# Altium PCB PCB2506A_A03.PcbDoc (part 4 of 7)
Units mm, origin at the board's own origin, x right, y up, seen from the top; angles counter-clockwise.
Board outline 115 x 60 mm, 6 copper layers (Top Layer, Signal Layer 2, Signal Layer 3, Signal Layer 4, Signal Layer 5, Bottom Layer), stack 1.555 mm thick; 376 components, 290 nets, 1297 pads, 901 vias.
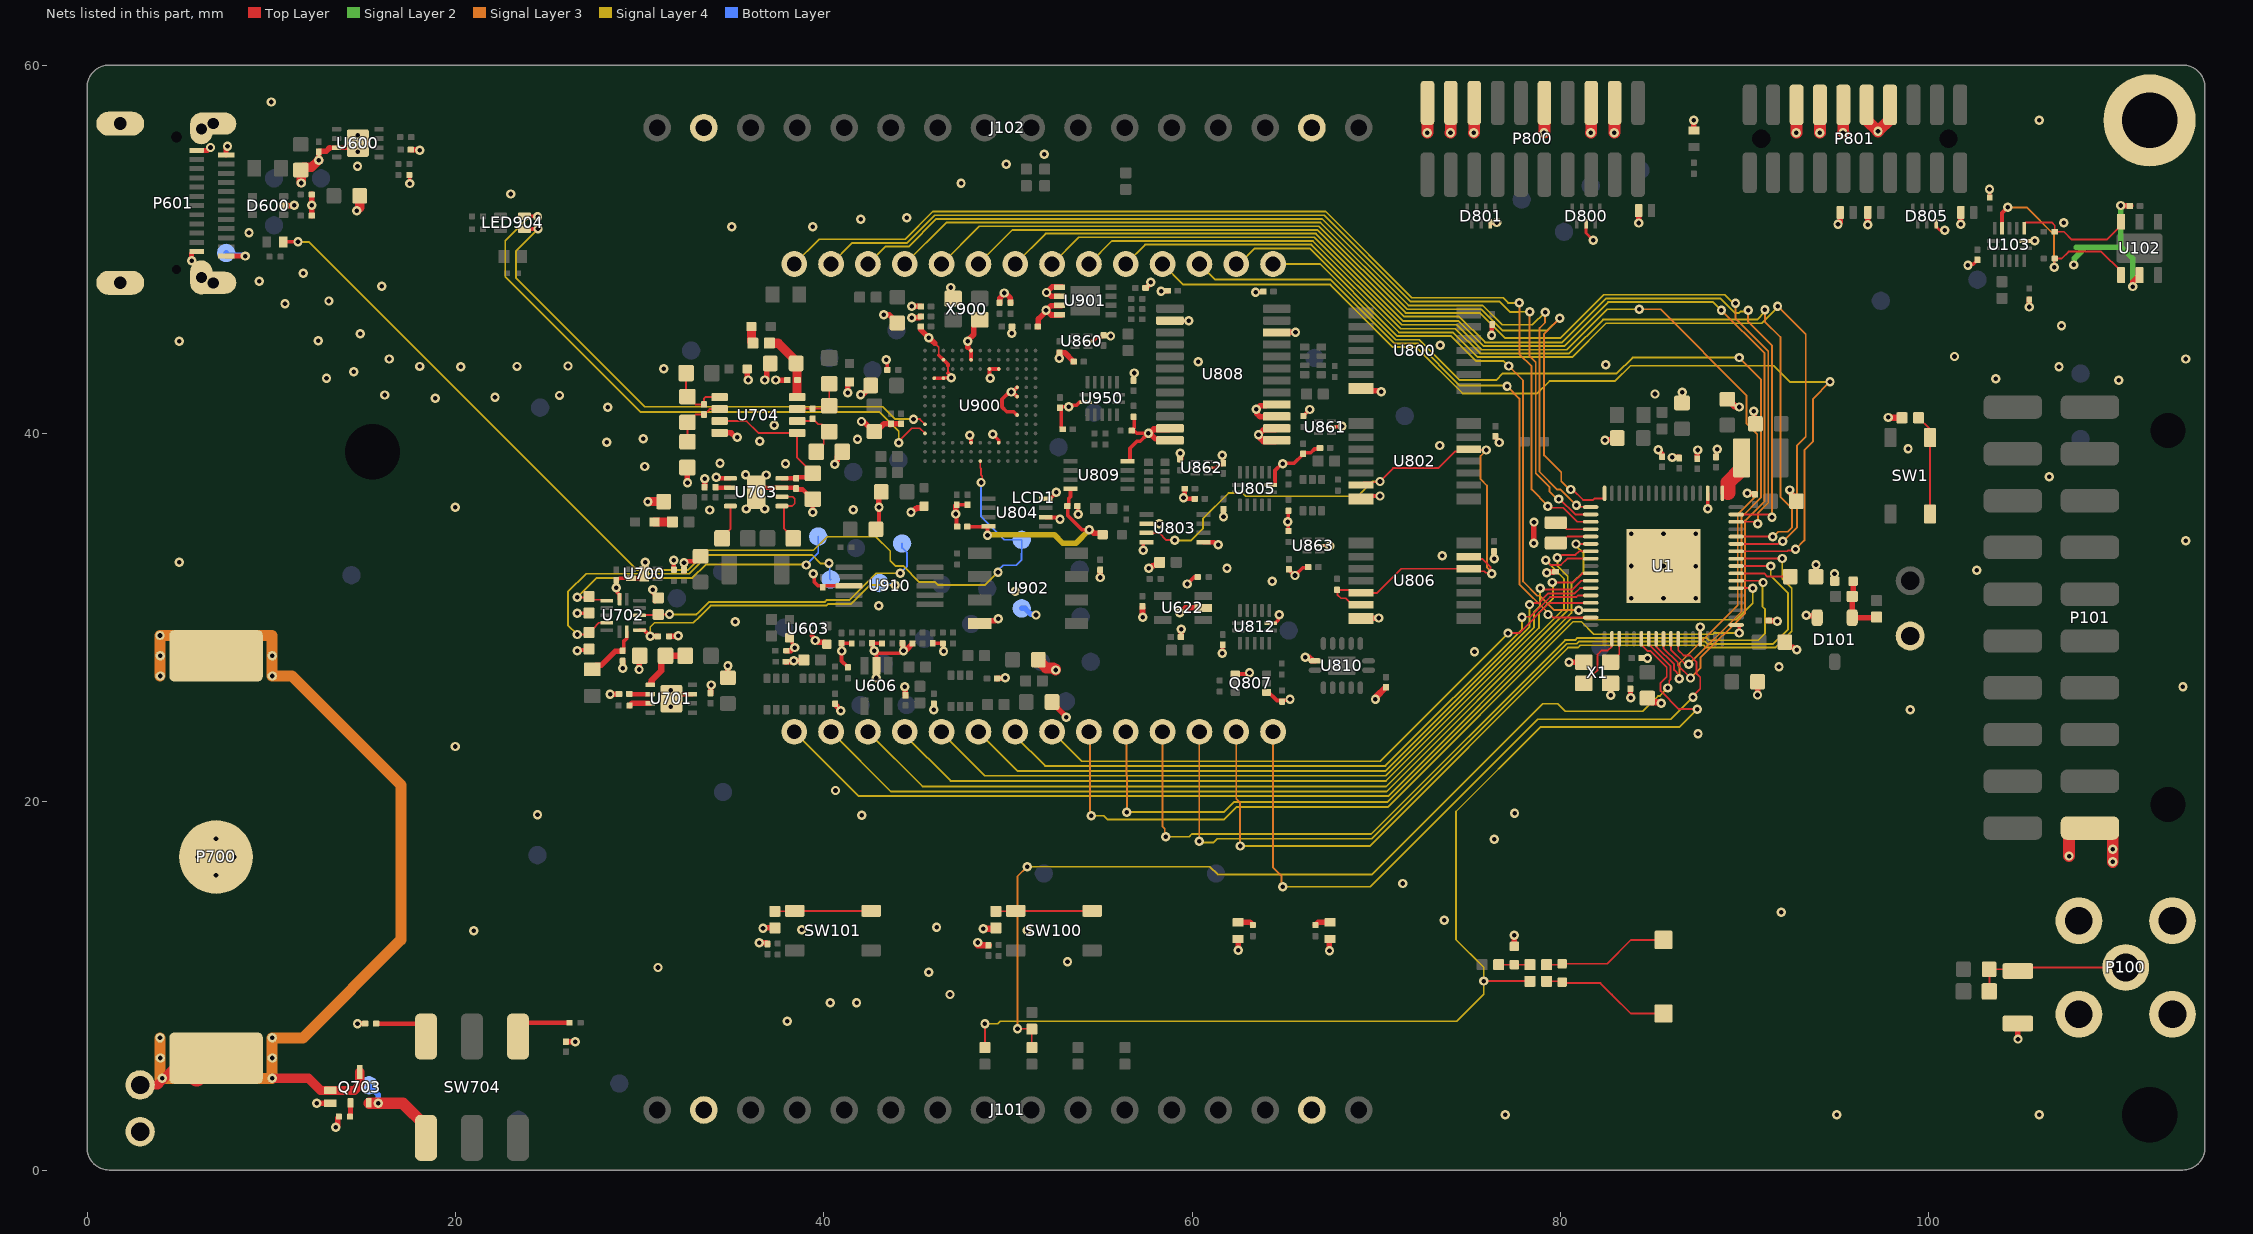
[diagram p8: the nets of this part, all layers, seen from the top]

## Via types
v1: diameter 0.508, hole 0.25, Top Layer to Bottom Layer, tented both sides, 901 vias

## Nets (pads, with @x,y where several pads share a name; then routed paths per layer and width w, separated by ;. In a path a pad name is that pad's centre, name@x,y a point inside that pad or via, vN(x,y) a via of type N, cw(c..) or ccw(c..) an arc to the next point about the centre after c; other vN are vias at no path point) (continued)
GND: C1.2 C2.2 C3.2 C4.2 C5.2 C6.2 C8.2 C9.2 C10.2 C12.2 C13.2 C15.2 C16.2 C17.2 C18.2 C102.2 C103.2 C110.2 C115.2 C117.2 C123.2 C130.2 C501.1 C600.2 C602.2 C607.2 C608.2 C609.2 C610.2 C611.2 C621.2 C625.2 C632.2 C635.2 C638.2 C641.2 C652.2 C653.2 C655.2 C660.2 C673.2 C674.2 C700.2 C701.2 C702.2 C703.2 C705.2 C706.2 C707.2 C708.2 C714.2 C720.2 C724.2 C728.2 C729.2 C730.2 C731.2 C800.2 C803.2 C804.2 C805.2 C806.2 C807.2 C808.2 C809.2 C810.2 C827.2 C828.2 C860.2 C861.2 C862.2 C863.2 C864.2 C865.2 C866.2 C867.2 C900.2 C901.2 C902.2 C903.2 C904.2 C905.2 C906.2 C907.2 C908.2 C909.2 C910.2 C911.2 C914.2 C921.2 C922.2 C924.2 C925.2 C926.2 C927.2 C950.2 C951.2 C952.2 D101.2 D600.2 D703.2 D800.6 D801.7 D805.7 D806.2 D807.2 D808.2 D809.2 J101.2 J101.15 J102.2 J102.15 LED100.2 LED101.2 LED900.2 M1.1 P100.2 P100.3 P100.4 P100.5 P101.1 P601.25@1.8,56.82 P601.26@1.8,48.18 P601.27@6.2,56.525 P601.27@6.85,56.82 P601.28@6.2,48.475 P601.28@6.85,48.18 P601.A1 P601.A12 P601.B1 P601.B12 P700.2 P800.3 P800.5 P800.9 P800.15 P800.17 P800.19 P801.7 P801.9 P801.11 P801.13 P801.15 Q807.1 Q807.4 R7.1 R104.2 R105.2 R112.2 R120.1 R602.1 R620.1 R621.1 R623.1 R628.2 R631.1 R634.1 R637.1 R640.1 R674.2 R688.2 R691.2 R703.1 R705.1 R706.1 R707.1 R708.1 R718.1 R760.1 R763.1 R767.1 R771.1 R792.1 R794.2 R814.1 R839.1 R850.1 R851.1 R852.1 R853.1 R930.2 R931.2 R950.2 R981.2 R985.2 ST701.1 TPH100.1 TPJ614.1 TPJ913.1 U1.31 U1.54 U1.69 U102.2 U103.7 U600.3 U600.9 U603.A1 U606.2 U622.2 U700.2 U700.5 U701.3 U701.9 U702.7 U703.3 U703.5 U703.9 U704.4 U800.7 U802.7 U803.2 U803.4 U803.5 U804.2 U804.4 U805.7 U806.7 U808.2 U808.11 U808.12 U808.13 U808.14 U808.15 U808.16 U808.22 U809.4 U810.7 U812.7 U860.2 U861.2 U862.2 U863.2 U900.C5 U900.C8 U900.F3 U900.H3 U900.J3 U900.K11 U900.K12 U900.L5 U900.L6 U900.M8 U900.M11 U900.N8 U901.1 U901.2 U901.3 U901.4 U902.4 U910.3 U950.7 X1.2 X1.4 X900.2 X900.4 | length 201.6
  Top Layer w0.1: 46.025,44.9 46.25,44.675 46.25,44.25 ; 46.75,43.275 46.75,43.674
  Top Layer w0.15: U862.2@60.873,38.135 61.325,38.135 61.405,38.215 ; v1@65.209,35.211 v1@65.284,35.136 ; U863.2@66.936,33.913 67.448,33.913 v1(67.475,33.885) ; D800.6@81.4,51.385 81.4,50.879 v1(81.788,50.491) ; D805.7@100.4,51.385 100.4,51.25 100.6,51.05 v1@101.05,51.05
  Top Layer w0.2: R602.1@17.5,54.035 17.513,54.022 17.513,53.582 v1(17.526,53.569) ; v1(26.61,28.194) 26.658,28.241 27.208,28.241 R705.1@27.255,28.289 ; v1(26.61,30.226) 26.622,30.238 27.065,30.238 R706.1@27.077,30.226 ; v1(28.735,31.618) 28.792,31.559 28.792,31.363 28.911,31.244 U702.7@28.911,31.004 ; v1(28.735,31.618) 28.734,31.619 28.734,32.032 C708.2@28.733,32.033 28.733,32.053 28.793,32.113 28.889,32.113 28.91,32.134 U700.2@29.533,32.134 ; C609.2@38.144,28.9 38.294,28.75 38.294,28.591 38.43,28.455 v1(38.43,28.372) ; 39.345,29.026 U603.A1@39.345,29.185 ; v1(39.432,32.38) 39.491,32.321 39.491,31.927 39.692,31.725 39.886,31.725 39.946,31.665 C922.2@39.946,31.645 ; C922.2@40.006,31.72 U910.3@41.374,31.72 ; R674.2@41.313,27.3 40.969,27.643 v1(40.969,28.184) C638.2@40.969,28.615 40.982,28.603 41.507,28.603 R637.1@41.519,28.59 ; C900.2@42.55,42.6 C900.2@42.6,42.6 ; v1@42.628,28.335 42.628,28.607 42.632,28.603 43.157,28.603 R640.1@43.169,28.59 ; C921.2@42.834,34.792 43,34.958 v1(43,36) ; v1(42.85,26.721) 42.856,26.727 U606.2@42.856,27.227 ; U606.2@42.861,27.242 42.861,28.004 42.747,28.118 v1(42.747,28.202) 42.83,28.202 42.965,28.067 44.128,28.067 44.264,28.203 v1(44.33,28.203) ; v1@43.3,44 v1@43.4,43.9 ; v1(43.4,44) v1@43.4,43.9 ; R763.1@43.45,43.45 43.45,43.85 v1@43.4,43.9 ; C632.2@45.919,28.615 45.932,28.603 46.457,28.603 R631.1@46.469,28.59 46.492,28.567 46.492,28.184 v1(46.507,28.169) ; U900.K12@46,43 U900.K11@46.5,43 46.525,43.025 v1(46.925,43.025) 46.925,43.1 46.75,43.275 ; 46.25,44.25 U900.M11@46.5,44 46.75,43.75 46.75,43.674 ; v1(47.175,35.625) 47.208,35.592 47.208,34.969 C804.2@47.241,34.936 ; C927.2@47.175,36.075 C927.2@47.225,36.125 C926.2@47.808,36.125 ; 47.828,44.667 47.995,44.5 U900.N8@48,44.5 U900.M8@48,44 ; v1(47.925,39.9) 47.925,39.875 48,39.8 U900.C8@48,39.5 ; v1(49.05,43) 49,43.05 U900.L6@49,43.5 U900.L5@49.5,43.5 ; v1(49.172,39.954) 49.5,39.626 U900.C5@49.5,39.5 ; U900.F3@50.5,41 50.318,41.182 49.942,41.182 49.682,41.442 49.682,41.859 49.932,42.109 49.951,42.109 50.092,42.25 v1(50.175,42.25) 50.2,42.25 v1@50.225,42.275 ; U900.H3@50.5,42 v1@50.225,42.275 ; U900.J3@50.5,42.5 50.275,42.275 v1@50.225,42.275 ; U804.2@52.053,35.454 52.069,35.439 52.728,35.439 v1(52.829,35.338) v1@52.834,35.333 ; U804.4@52.053,36.454 52.303,36.454 52.622,36.773 v1(52.622,36.796) ; C911.2@52.825,41.375 C911.2@52.893,41.375 ; C909.2@52.975,40.225 52.893,40.307 C911.2@52.893,41.375 ; v1@53.25,41.5 v1@53.25,41.45 ; C810.2@53.775,36.055 53.795,36.035 53.795,35.624 v1(53.816,35.604) ; U950.7@54.24,41.7 53.9,41.7 53.73,41.53 53.38,41.53 v1(53.3,41.45) ; U860.2@54.5,45 54.627,45 54.88,45.253 55.14,45.253 55.2,45.313 C862.2@55.2,45.325 v1@55.45,45.325 ; v1@55.45,45.307 55.557,45.307 v1(55.575,45.288) ; U809.4@56.498,38.485 56.606,38.485 56.631,38.51 56.631,39.198 57.011,39.577 57.194,39.577 57.532,39.915 57.532,40.001 v1@57.517,40.016 ; R981.2@56.721,40.149 56.731,40.149 R981.2@56.791,40.209 ; R950.2@56.825,40.9 56.858,40.867 56.858,40.286 56.791,40.219 R981.2@56.791,40.209 ; C950.2@56.825,42.875 56.848,42.898 56.848,43.259 v1(56.871,43.282) ; v1(57.356,33.655) 57.356,34.074 57.381,34.099 U803.4@57.521,34.099 ; U803.2@57.521,35.099 U803.2@57.521,35.099 58.215,35.101 v1(58.217,35.103) ; v1(57.633,40.016) v1@57.517,40.016 ; U808.2@58.8,46.125 v1@59.816,46.126 ; v1(59.538,36.5) v1@59.609,36.498 ; v1(59.741,31.826) 60.115,32.2 R688.2@60.304,32.2 ; 61.405,38.215 61.485,38.295 61.635,38.295 61.695,38.355 C860.2@61.695,38.375 61.667,38.403 61.667,38.78 v1(61.639,38.808) ; v1(61.646,28.067) 61.658,28.079 61.658,28.518 C828.2@61.67,28.53 ; C800.2@61.707,35.886 61.708,35.885 v1(61.709,35.471) v1(61.709,35.471) ; Q807.4@62.35,26.938 62.966,26.938 63.036,27.007 v1(63.119,27.007) ; v1(63.449,47.676) C806.2@63.872,47.676 ; v1@63.755,39.75 64.475,39.75 U808.13@64.6,39.625 ; Q807.1@64.022,25.938 Q807.1@64.05,25.938 64.172,25.938 64.498,25.612 64.615,25.494 64.83,25.494 R839.1@64.867,25.457 ; U812.7@64.285,29.7 64.525,29.7 64.676,29.851 64.676,30.091 v1(64.735,30.15) ; U805.7@64.285,37.2 64.505,37.2 64.505,37.987 64.869,38.351 v1(64.921,38.351) ; R839.1@64.835,25.425 R839.1@64.867,25.457 ; R839.1@64.888,25.436 R839.1@64.867,25.457 ; v1@64.897,38.379 65.541,38.379 66.036,38.875 C865.2@66.036,38.895 66.088,38.947 66.447,38.947 66.654,39.154 66.89,39.154 C864.2@66.95,39.214 ; R814.1@65.232,35.8 65.217,35.785 65.217,35.22 65.209,35.211 v1(65.202,35.204) 65.221,35.185 65.221,34.717 R853.1@65.24,34.698 ; C867.2@65.316,32.627 65.316,32.535 65.567,32.283 v1(65.591,32.283) 66.009,32.702 66.243,32.702 C866.2@66.287,32.745 ; v1(65.321,25.571) 65.237,25.571 65.172,25.506 64.916,25.506 R839.1@64.867,25.457 ; R851.1@66.048,40.949 66.048,40.959 66.386,41.297 v1(66.396,41.297) ; U861.2@67.573,40.343 67.594,40.364 68.125,40.364 v1(68.146,40.385) ; U802.7@69.175,36.45 69.326,36.601 v1(70.206,36.601) ; D801.7@76.2,51.385 76.2,51.415 76.205,51.42 76.509,51.42 v1(76.545,51.456) ; C809.2@76.402,33.588 v1(76.402,33.185) 76.486,33.185 v1@76.549,33.122 ; U1.31@87.6,28.85 87.6,29.485 v1(87.605,29.489) ; U1.54@88,36.75 88,35.927 v1(88.011,35.916) ; C9.2@88.452,38.72 88.463,38.731 88.463,39.085 v1(88.519,39.141) ; v1(102.133,49.124) 102.192,49.183 102.427,49.183 102.648,49.403 C952.2@102.648,49.423 ; v1(103.302,53.264) 103.311,53.254 103.311,52.821 R985.2@103.321,52.812 ; U103.7@105.273,50.451 105.738,50.451 v1(105.757,50.47) ; C911.2@52.893,41.375 52.968,41.45 v1@53.25,41.45 ; v1@53.25,41.45 53.25,41.399 v1(53.3,41.45) ; v1@53.25,41.45 v1(53.3,41.45) ; R981.2@56.791,40.209 56.791,40.089 56.921,40.089 56.995,40.016 v1@57.517,40.016
  Top Layer w0.25: 13.175,55.513 U600.3@13.55,55.513 U600.9@14.75,55.513 ; U700.2@29.533,32.134 30.133,32.134 30.258,32.259 U700.5@30.258,32.384 30.281,32.407 30.281,32.988 v1(30.303,33.01) ; v1(30.709,31.521) 30.758,31.472 30.758,31.328 R707.1@31.014,31.071 R707.1@30.839,30.896 ; U701.9@31.728,25.592 31.978,25.842 U701.3@32.878,25.842 ; R760.1@31.861,32.6 31.862,32.602 31.862,33.104 v1(31.863,33.106) ; C701.2@32.411,32.575 v1(32.411,32.971) 32.481,32.971 32.566,33.056 33.036,33.056 C700.2@33.311,33.331 ; v1@34.279,37.558 U703.5@34.929,37.558 ; U703.9@36.329,36.808 36.579,37.058 U703.3@37.729,37.058 38.469,37.058 38.504,37.023 C729.2@38.504,37.008 38.504,36.988 38.539,36.953 38.859,36.953 39.379,36.433 R718.1@39.404,36.433 v1(39.404,35.729) ; 39.345,29.026 39.548,28.823 v1(39.548,28.753) ; v1@59.592,36.445 C807.2@60.145,36.445 ; v1@59.609,36.498 C861.2@59.609,36.994 ; U803.5@60.621,34.099 61.208,34.099 61.347,33.96 v1(61.417,33.96) ; v1(76.265,45.336) 76.283,45.354 76.283,45.898 C803.2@76.301,45.916 ; C805.2@76.479,39.841 76.479,39.755 v1@76.684,39.549 ; C8.2@83.8,26.138 83.81,26.128 83.81,25.654 v1(83.82,25.644)
  Top Layer w0.27: v1(5.675,49.375) 5.675,49.775 5.775,49.875 P601.B1@5.95,49.875 ; P601.B12@5.95,55.375 6.55,55.375 v1(6.7,55.525) ; P601.A12@7.55,49.625 8.579,49.625 v1(8.585,49.632) ; P601.A1@7.55,55.125 7.55,55.5 7.625,55.575 v1(7.625,55.6) ; v1(14.681,7.95) R794.2@15.1,7.95 R794.2@15.11,7.95
  Top Layer w0.3: D600.2@10.675,52.375 11.225,52.375 v1(11.25,52.4) ; R621.1@12.2,51.825 12.2,51.9 v1(12.2,52.4) 12.2,52.9 R620.1@12.2,52.975 ; v1(12.475,3.625) D703.2@13.2,3.625 ; v1(12.573,54.839) 12.573,55.301 12.606,55.334 12.996,55.334 13.175,55.513 ; v1(13.501,2.325) 13.6,2.424 13.6,2.825 R792.1@13.675,2.9 ; U600.9@14.732,55.296 14.75,55.314 U600.9@14.75,55.513 ; C602.2@17.575,55.411 17.585,55.401 18.03,55.401 v1(18.059,55.372) ; C706.2@26,6.975 v1(26.5,6.975) ; v1(28.397,25.832) 28.413,25.847 28.874,25.847 C705.2@28.884,25.857 ; v1(29.083,27.254) C707.2@29.083,27.64 ; v1(29.972,27.178) 29.989,27.195 29.989,27.907 R703.1@30.006,27.924 ; R708.1@31.593,28.981 31.603,28.991 32.09,28.991 v1(32.106,29.007) ; v1(32.6,37.325) R767.1@32.6,38.15 ; C728.2@33.529,37.083 33.534,37.088 33.534,37.536 v1(33.538,37.54) ; C702.2@33.858,25.904 33.868,25.914 33.868,26.315 v1(33.893,26.34) ; v1(34.163,37.617) 34.219,37.617 v1@34.279,37.558 ; U704.4@34.345,40.025 34.975,40.025 35.2,39.8 v1(35.3,39.8) ; C703.2@34.798,26.619 C703.2@34.798,26.735 v1(34.798,27.381) ; C720.2@35.85,43.5 35.85,42.95 v1(35.9,42.9) ; v1(36.5,12.35) 36.875,12.35 C103.2@36.95,12.275 ; v1(36.7,13.125) 36.725,13.15 R105.2@37.35,13.15 ; v1(36.8,42.9) 36.9,43 36.9,43.6 C731.2@37.1,43.8 ; v1(37.4,42.9) C730.2@38.025,42.9 ; C610.2@37.944,27.6 37.944,27.58 37.954,27.59 38.294,27.59 38.304,27.6 38.319,27.6 v1(38.379,27.661) 38.468,27.661 38.475,27.668 38.887,27.668 R628.2@38.919,27.7 R628.2@38.919,27.668 ; R623.1@37.969,28.2 38.202,28.2 38.374,28.372 v1(38.43,28.372) ; v1(39.548,28.753) 39.604,28.753 39.707,28.65 40.069,28.65 C608.2@40.169,28.55 40.176,28.543 C608.2@40.176,28.534 ; v1(40.6,38.333) 40.6,38.389 40.725,38.514 40.725,38.725 R771.1@41,39 ; C621.2@40.619,25.315 40.619,25.295 40.703,25.212 40.703,25.206 v1@40.919,24.989 ; v1(40.919,24.933) v1@40.959,24.973 ; v1(41.3,42.2) 41.3,42.7 C724.2@41.4,42.8 ; v1(42,42.1) 42.1,42.1 C900.2@42.55,42.55 ; v1(42.05,40.65) 42.15,40.65 C907.2@42.75,40.05 ; C907.2@42.75,40 43.275,40.525 C924.2@43.65,40.525 ; v1(43,36) C902.2@43,36.95 ; v1@43.3,46.45 43.55,46.45 C903.2@44,46 ; C924.2@43.6,40.475 C924.2@43.65,40.525 ; C925.2@44.2,40.525 C924.2@43.65,40.525 ; C635.2@44.269,28.615 44.279,28.605 44.279,28.31 44.33,28.259 v1(44.33,28.203) ; v1@44.384,28.205 44.422,28.243 44.482,28.243 44.819,28.58 R634.1@44.819,28.59 ; v1(44.399,26.238) 44.43,26.207 44.43,25.794 C660.2@44.44,25.784 ; v1(44.741,35.727) 44.798,35.727 44.97,35.9 45.016,35.9 45.066,35.95 45.35,35.95 C901.2@45.45,36.05 ; v1(44.775,46.275) 45.2,46.275 C905.2@45.275,46.35 ; v1(44.775,46.9) C906.2@45.275,46.9 ; C904.2@45.275,45.8 45.275,45.625 v1(45.7,45.2) ; v1@45.7,45.15 v1(45.7,45.2) ; v1(45.98,24.987) C674.2@45.98,25.318 ; 46.025,44.9 45.925,45 45.9,45 v1(45.7,45.2) ; v1(46.126,13.183) v1@46.143,13.166 ; X900.4@46.9,47.2 v1@46.9,47.9 ; v1(47.175,35.625) C927.2@47.175,36.075 ; 47.828,44.667 v1(47.828,45.009) ; v1@47.828,45.065 48.15,45.387 48.15,45.95 X900.2@48.3,46.1 ; U902.4@48.3,29.684 48.45,29.834 49.321,29.834 49.423,29.936 v1(49.479,29.936) ; C673.2@49.413,26.687 49.423,26.697 49.752,26.697 49.795,26.741 v1(49.852,26.741) ; R931.2@49.55,47.1 49.56,47.11 49.56,47.345 49.8,47.585 v1(49.8,47.625) 49.84,47.585 49.9,47.585 50.14,47.345 50.14,47.11 R930.2@50.15,47.1 ; C910.2@50.216,45.681 v1(50.217,45.439) v1(50.217,45.439) ; C908.2@51.625,45.8 51.645,45.8 51.655,45.81 51.655,46.214 52.07,46.629 v1(52.07,46.685) 52.096,46.685 52.35,46.939 U901.3@52.901,46.939 ; v1@52.095,46.654 52.127,46.654 52.35,46.431 U901.4@52.898,46.431 ; C655.2@52.395,25.415 52.395,25.39 53.164,24.621 v1(53.164,24.596) ; U901.2@52.792,47.458 52.344,47.458 52.152,47.65 v1(52.095,47.65) 52.4,47.955 U901.1@52.921,47.955 ; v1(52.798,44.078) 52.798,44.173 52.799,44.174 52.799,44.399 R850.1@52.8,44.4 52.8,44.39 52.81,44.38 53.095,44.38 53.545,43.93 53.545,43.91 53.555,43.9 C863.2@53.575,43.9 ; v1(55.013,32.178) C914.2@55.013,32.589 ; C653.2@57.3,30.552 57.31,30.542 57.31,30.041 v1(57.328,30.023) ; C951.2@57.476,47.904 57.496,47.904 57.76,48.168 v1(57.76,48.209) ; v1(57.653,32.681) 57.709,32.681 57.835,32.807 57.916,32.807 57.959,32.85 58.092,32.85 R691.2@58.242,33 ; v1@57.701,40.005 57.714,40.005 58.019,39.7 58.293,39.7 U808.12@58.369,39.625 ; v1(58.318,47.727) 58.332,47.74 58.665,47.74 C808.2@58.675,47.75 ; v1(59.323,30.27) 59.379,30.27 59.631,30.521 60.593,30.521 U622.2@60.638,30.476 ; C652.2@59.397,28.945 59.404,28.952 59.404,29.364 v1(59.411,29.371) ; v1(62.509,11.938) LED101.2@62.509,12.558 ; U808.16@64.022,41.543 64.022,41.533 64,41.511 63.7,41.511 63.5,41.312 v1(63.486,41.312) 63.526,41.272 63.526,41.071 63.697,40.9 64.575,40.9 U808.15@64.6,40.925 ; U808.14@64.591,40.284 64.506,40.2 63.881,40.2 v1(63.61,39.929) 63.61,39.873 63.705,39.777 63.705,39.726 63.881,39.55 64.525,39.55 U808.13@64.6,39.625 ; U808.22@64.921,45.483 65.609,45.483 v1(65.617,45.491) ; U810.7@66.565,27.643 U810.7@66.685,27.643 ; v1(67.462,11.913) LED100.2@67.462,12.55 ; U806.7@69.064,29.964 70.128,29.964 v1(70.143,29.979) ; U800.7@69.187,42.448 69.322,42.312 70.235,42.312 v1(70.275,42.273) ; C123.2@77.5,12.15 v1(77.5,12.75) ; v1(78.562,34.036) 78.565,34.039 78.565,35.184 v1(78.568,35.187) ; v1(79.257,32.436) 79.297,32.476 79.617,32.476 C1.2@79.638,32.497 ; v1(80.468,27.583) 80.473,27.579 81.271,27.579 X1.4@81.275,27.575 ; v1(82.423,39.624) 82.463,39.664 83.01,39.664 C5.2@83.097,39.75 ; v1(82.728,25.781) 82.726,25.782 82.726,26.334 82.688,26.372 X1.2@82.733,26.417 ; v1(84.25,51.425) D809.2@84.25,52.1 ; C4.2@84.422,27.804 84.432,27.794 84.725,27.794 v1(84.735,27.783) ; v1(85.312,39.123) 85.312,39.079 85.502,38.889 C6.2@85.502,38.729 ; v1(86.077,38.696) 86.099,38.718 C18.2@86.455,38.718 ; C17.2@86.608,41.655 86.611,41.658 86.611,42.237 v1(86.614,42.24) ; LED900.2@87.25,56.45 v1(87.25,57) ; C13.2@87.433,38.629 87.443,38.639 87.443,39.081 v1(87.462,39.101) ; v1(90.145,36.754) 90.176,36.723 90.557,36.723 90.567,36.713 C15.2@90.567,36.693 ; v1(90.498,41.199) 90.538,41.159 90.538,40.581 C12.2@90.595,40.525 ; v1(90.709,25.796) C130.2@90.709,26.515 ; C2.2@91.315,29.844 91.325,29.834 91.75,29.834 v1(91.779,29.804) ; C117.2@92.191,28.668 92.191,28.643 92.441,28.393 92.632,28.393 92.781,28.245 v1(92.837,28.245) ; v1(93.361,30.128) 93.401,30.088 93.862,30.088 D101.2@93.95,30 ; C501.1@93.883,32.226 v1(93.883,32.868) ; v1(94.889,32.391) 94.894,32.385 94.894,31.981 C115.2@94.9,31.975 ; v1(95.075,51.35) 95.2,51.475 D806.2@95.2,52 ; v1(96.7,51.325) D807.2@96.7,52 ; v1(101.75,51.361) D808.2@101.75,52.209 ; v1(104.851,7.112) R120.1@104.851,7.874 ; v1(105.461,46.866) R112.2@105.461,47.274 ; v1@110.475,52.375 C110.2@110.975,52.375 ; v1(111.075,47.975) 111.075,48.225 U102.2@111.45,48.6
  Top Layer w0.35: v1(48.362,12.356) 48.362,12.217 48.38,12.199 C102.2@48.95,12.199 ; v1(48.666,13.106) 49.306,13.106 R104.2@49.35,13.15 ; v1(57.633,40.016) 57.644,40.005 57.701,40.005 57.921,40.225 58.75,40.225 U808.11@58.8,40.275 ; R852.1@59.354,38.597 v1(59.354,38.928) ; v1(59.538,36.5) v1(59.538,36.5) v1@59.592,36.445 ; v1(66.142,27.844) 66.172,27.813 66.365,27.813 U810.7@66.51,27.668 ; v1(69.959,25.571) 69.989,25.601 69.989,25.682 C827.2@70.52,26.213 ; v1(76.684,39.506) v1@76.684,39.549 ; C3.2@84.725,25.629 84.95,25.404 85.373,25.404 85.428,25.349 v1(85.471,25.349) ; C10.2@89.067,41.856 89.092,41.856 89.482,41.466 89.683,41.466 v1(89.713,41.435) ; v1(92.456,36.932) 92.486,36.901 92.486,36.774 92.593,36.668 92.593,36.541 C16.2@92.818,36.316 ; v1(97.815,40.869) 97.841,40.843 98.543,40.843 R7.1@98.55,40.85
  Top Layer w0.5: v1(11.625,53.6) 11.625,54.175 11.5,54.3 C611.2@11.6,54.3 11.75,54.45 12.182,54.45 12.571,54.839 v1(12.573,54.839) ; v1(14.65,52.1) 14.8,52.25 C607.2@14.8,52.9 ; v1(30.454,36.296) C714.2@31.311,36.296
  Top Layer w0.6: C625.2@51.656,27.712 51.656,27.687 52.084,27.259 52.484,27.259 v1(52.59,27.153) v1@52.59,27.215
  Top Layer w0.635: v1(72.765,56.325) 72.785,56.345 P800.19@72.785,57.95 ; v1(74.035,56.325) 74.055,56.345 P800.17@74.055,57.95 ; v1(75.305,56.325) 75.325,56.345 P800.15@75.325,57.95 ; v1(79.115,56.325) 79.135,56.345 P800.9@79.135,57.95 ; v1(81.655,56.325) 81.675,56.345 P800.5@81.675,57.95 ; v1(82.925,56.325) 82.945,56.345 P800.3@82.945,57.95 ; v1(92.81,56.325) 92.835,56.325 92.825,56.335 P801.15@92.825,57.841 ; v1(94.08,56.325) 94.105,56.325 94.095,56.335 P801.13@94.095,57.841 ; v1(95.35,56.325) 95.375,56.325 95.365,56.335 P801.11@95.365,57.841 ; P801.9@96.635,57.841 96.635,57.015 v1(97.25,56.4) 97.905,57.055 P801.7@97.905,57.841 ; v1(107.625,17.05) 107.625,18.25 107.945,18.57 P101.1@108.76,18.57 109.705,18.57 110,18.275 v1(110,17.425) v1(110,16.75) v1@110,16.725
  Signal Layer 2 w0.3: v1(107.886,49.149) 107.917,49.18 107.917,49.514 108.503,50.1 ; 108.015,50.1 108.503,50.1 ; 110.428,50.1 110.428,50.317 v1@110.428,52.372 ; v1(111.075,47.975) 111.075,49.5 110.475,50.1 110.211,50.1 108.503,50.1
  Signal Layer 3 w0.2: v1@49.15,39.9 49.172,39.922 v1(49.172,39.954)
  Bottom Layer w0.3: TPJ614.1@7.55,49.8 7.679,49.671 8.545,49.671 v1(8.585,49.632) ; TPJ913.1@50.751,30.501 50.941,30.501 51.263,30.179 51.485,30.179 v1(51.525,30.139)
  other v1: 77,3 95,3 106,3 38.024,8.077 40.361,9.093 41.783,9.093 46.856,9.529 45.695,10.744 31,11 53.238,11.303 21,13 51.054,13.005 38.811,13.056 73.692,13.57 92,14 71.44,15.56 7,16 6,17 8,17 76.403,17.958 7,18 42.06,19.261 24.454,19.299 77.514,19.373 40.638,20.607 20,23 87.478,23.698 99,25 31.7,25.15 31.7,26.05 113.809,26.248 91.872,27.33 75.336,28.143 35.204,29.769 42.992,30.644 83.85,31.05 85.6,31.05 87.348,31.05 50.407,31.435 64.35,31.977 102.616,32.563 61.9,32.681 83.85,32.8 85.6,32.8 87.348,32.798 5,33 73.584,33.35 113.961,34.173 83.85,34.55 85.6,34.55 87.348,34.55 33.807,35.839 41.605,35.865 35.8,35.9 36.8,35.9 20,36 106.553,37.643 35.755,37.756 36.881,37.744 30.277,38.202 37.922,38.354 34.366,38.379 98.882,39.167 73.457,39.345 28.219,39.522 36.525,39.573 41.834,39.675 30.195,39.72 37.313,40.437 28.27,41.427 18.898,41.91 22.149,41.961 25.654,42.062 16.154,42.088 85.141,42.139 110.329,42.885 103.649,42.961 13,43 14.478,43.358 31.318,43.51 20.295,43.612 107.078,43.622 18.059,43.637 23.343,43.637 26.111,43.663 82.474,43.727 60.33,43.9 16.408,44.044 113.97,44.044 101.406,44.178 73.482,44.78 5,45 12.548,45.034 14.834,45.415 107.217,45.843 59.817,46.126 43.25,46.45 10.744,47.041 13.132,47.193 46.9,47.925 16,48 9.347,48.26 11.735,48.692 8.788,50.902 100.875,51.025 35,51.218 39.394,51.218 107.34,51.435 42.012,51.638 44.501,51.714 110.425,52.375 23,53 47.458,53.591 14.681,54.508 49.911,54.61 51.968,55.169 14.7,55.3 14.7,56.2 106,57 10,58
HFXTAL_I: U1.19 X1.1 | length 3.3
  Top Layer w0.1: X1.1@81.275,26.425 81.306,26.425 82.017,27.136 82.017,27.991 82.246,28.221 82.577,28.221 82.781,28.425 82.781,28.831 U1.19@82.8,28.85
HFXTAL_O: U1.20 X1.3 | length 1.5
  Top Layer w0.1: X1.3@82.725,27.575 82.756,27.575 83.2,28.019 U1.20@83.2,28.85
LCD_COM0: LCD1.28 U1.3 | length 57
  Top Layer w0.1: v1(79.324,36.043) 79.4,35.966 80.162,35.966 80.929,35.2 U1.3@81.65,35.2
  Signal Layer 3 w0.1: v1(77.775,47.092) 77.775,44.298 78.435,43.637 78.435,36.96 79.324,36.071 v1(79.324,36.043)
  Signal Layer 4 w0.1: LCD1.28@38.4,49.2 39.746,50.546 44.425,50.546 45.929,52.05 67.25,52.05 71.933,47.368 76.889,47.368 77.165,47.092 v1(77.775,47.092)
LCD_COM1: LCD1.27 U1.2 | length 54.2
  Top Layer w0.1: v1(79.908,36.435) 79.976,36.435 80.812,35.6 U1.2@81.65,35.6
  Signal Layer 3 w0.1: v1(78.334,46.609) 78.334,44.196 78.664,43.866 78.664,37.843 79.407,37.1 79.407,36.849 79.82,36.435 v1(79.908,36.435)
  Signal Layer 4 w0.1: LCD1.27@40.4,49.2 41.546,50.346 44.526,50.346 46.03,51.85 67.168,51.85 71.85,47.168 76.687,47.168 77.257,46.597 77.788,46.597 77.8,46.609 v1(78.334,46.609)
LCD_COM2: LCD1.26 U1.1 | length 52.8
  Top Layer w0.1: v1(80.874,36.094) 80.948,36.019 81.631,36.019 U1.1@81.65,36
  Signal Layer 3 w0.1: v1(79.172,46.584) 79.172,46.025 78.867,45.72 78.867,37.922 79.84,36.95 80.017,36.95 v1@80.873,36.094
  Signal Layer 4 w0.1: LCD1.26@42.4,49.2 43.346,50.146 44.609,50.146 46.113,51.65 67.058,51.65 71.761,46.947 75.786,46.947 76.835,45.898 78.486,45.898 v1(79.172,46.584)
LCD_COM3: LCD1.25 U1.68 | length 51.8
  Top Layer w0.1: v1(80.569,36.957) 80.659,36.957 81.229,36.386 81.789,36.386 81.878,36.475 82.354,36.475 82.4,36.521 U1.68@82.4,36.75
  Signal Layer 3 w0.1: v1(79.959,46.253) 79.121,45.415 79.121,38.808 80.047,37.882 80.047,37.395 80.485,36.957 v1(80.569,36.957)
  Signal Layer 4 w0.1: LCD1.25@44.4,49.2 46.65,51.45 66.975,51.45 71.679,46.747 75.703,46.747 76.857,45.593 79.299,45.593 v1(79.959,46.253)
LCD_COM4: LCD1.24 U1.49 | length 61.8
  Top Layer w0.1: U1.49@89.55,35.2 90.521,35.2 90.618,35.103 v1(90.729,35.103)
  Signal Layer 3 w0.1: v1(89.51,47.066) 89.51,46.253 91.291,44.472 91.291,36.236 90.729,35.674 v1(90.729,35.103)
  Signal Layer 4 w0.1: LCD1.24@46.4,49.2 48.45,51.25 66.892,51.25 71.596,46.547 75.621,46.547 76.981,45.187 80.01,45.187 82.355,47.532 88.933,47.532 89.399,47.066 v1(89.51,47.066)
LCD_COM5: LCD1.23 U1.50 | length 60.2
  Top Layer w0.1: U1.50@89.55,35.6 91.349,35.6 91.491,35.458 v1(91.491,35.455)
  Signal Layer 3 w0.1: v1(90.195,46.685) 90.195,46.076 91.491,44.78 v1(91.491,35.455)
  Signal Layer 4 w0.1: LCD1.23@48.4,49.2 50.25,51.05 66.809,51.05 71.513,46.347 74.51,46.347 75.913,44.943 80.097,44.943 82.486,47.332 88.688,47.332 89.474,46.546 89.71,46.546 89.791,46.628 90.138,46.628 v1(90.195,46.685)
LCD_COM6: LCD1.22 U1.26 | length 68.1
  Top Layer w0.1: U1.26@85.6,28.85 85.6,28.344 86.379,27.565 86.379,27.413 87.067,26.725 v1(87.067,26.721)
  Signal Layer 3 w0.1: v1(87.067,26.721) 87.071,26.721 87.605,27.254 87.605,27.81 90.037,30.242 90.037,35.264 91.091,36.319 91.091,44.342 v1(88.748,46.685)
  Signal Layer 4 w0.1: LCD1.22@50.4,49.2 52.05,50.85 66.727,50.85 71.479,46.098 74.476,46.098 75.831,44.743 80.202,44.743 82.591,47.132 88.301,47.132 v1(88.748,46.685)
LCD_COM7: LCD1.21 U1.25 | length 63.8
  Top Layer w0.1: U1.25@85.2,28.85 85.219,28.831 85.219,28.42 86.179,27.461 86.179,27.156 86.462,26.873 v1(86.462,26.67)
  Signal Layer 3 w0.1: v1(84.277,46.739) 85.442,46.739 90.106,42.076 90.106,41.362 ; v1(86.462,26.67) 86.462,27.505 89.637,30.68 89.637,35.611 90.691,36.665 90.691,39.964 90.105,40.549 90.105,41.362
  Signal Layer 4 w0.1: LCD1.21@52.4,49.2 53.85,50.65 66.644,50.65 71.396,45.898 74.371,45.898 75.726,44.543 80.357,44.543 82.553,46.739 v1(84.277,46.739)
LCD_CP: C501.2 U1.42 | length 3
  Top Layer w0.1: U1.42@89.55,32.4 91.061,32.4 91.235,32.226 C501.2@92.483,32.226
LCD_SEG0: LCD1.1 U1.6 | length 52.8
  Top Layer w0.1: v1(80.848,33.993) 80.852,33.996 81.646,33.996 U1.6@81.65,34
  Signal Layer 4 w0.1: LCD1.1@38.4,23.8 41.894,20.306 70.656,20.306 80.6,30.25 80.6,31.831 81.263,32.495 81.263,33.489 80.848,33.904 v1(80.848,33.993)
LCD_SEG1: LCD1.2 U1.7 | length 50.5
  Top Layer w0.1: v1(79.837,33.253) 79.947,33.253 80.099,33.406 80.822,33.406 81.016,33.6 U1.7@81.65,33.6
  Signal Layer 4 w0.1: LCD1.2@40.4,23.8 43.651,20.549 70.561,20.549 80.4,30.387 80.4,32.247 79.837,32.81 v1(79.837,33.253)
LCD_SEG2: LCD1.3 U1.8 | length 48.8
  Top Layer w0.1: v1(79.204,33.105) 79.449,32.86 80.036,32.86 80.376,33.2 U1.8@81.65,33.2
  Signal Layer 4 w0.1: LCD1.3@42.4,23.8 45.372,20.828 70.543,20.828 80.2,30.484 80.2,32.11 v1(79.204,33.105)
LCD_SEG3: LCD1.4 U1.10 | length 44.3
  Top Layer w0.1: v1(79.569,31.909) 80.705,31.909 81.184,32.388 81.721,32.388 U1.10@81.744,32.41
  Signal Layer 4 w0.1: LCD1.4@44.4,23.8 44.4,23.621 46.888,21.133 70.533,21.133 78.842,29.441 78.842,30.277 79.594,31.029 79.594,31.883 v1(79.569,31.909)
LCD_SEG4: LCD1.5 U1.11 | length 42.3
  Top Layer w0.1: v1(78.904,31.589) 78.978,31.516 80.65,31.516 81.134,32 U1.11@81.867,32
  Signal Layer 4 w0.1: LCD1.5@46.112,24.043 48.743,21.412 70.53,21.412 78.562,29.445 78.562,30.302 78.904,30.644 v1(78.904,31.589)
LCD_SEG5: LCD1.6 U1.12 | length 39.2
  Top Layer w0.1: v1(78.324,30.706) 78.402,30.784 78.823,30.784 79.354,31.316 80.783,31.316 81.067,31.6 U1.12@81.839,31.6
  Signal Layer 4 w0.1: LCD1.6@48.4,23.8 50.534,21.666 70.501,21.666 78.334,29.499 78.334,30.697 v1(78.324,30.706)
LCD_SEG6: LCD1.7 U1.13 | length 36.4
  Top Layer w0.1: v1(77.92,30.017) 77.946,30.043 78.364,30.043 79.437,31.116 80.866,31.116 80.95,31.2 U1.13@81.65,31.2
  Signal Layer 4 w0.1: LCD1.7@50.4,23.8 50.4,23.565 52.019,21.946 70.497,21.946 77.92,29.369 v1(77.92,30.017)
LCD_SEG7: LCD1.8 U1.14 | length 33.5
  Top Layer w0.1: v1(77.155,29.159) 77.763,29.159 79.404,30.8 U1.14@81.606,30.8
  Signal Layer 4 w0.1: LCD1.8@52.4,23.8 54,22.2 70.231,22.2 77.155,29.124 v1(77.155,29.159)
LCD_SEG8: LCD1.9 U1.35 | length 45.2
  Top Layer w0.1: U1.35@89.55,29.6 89.667,29.6 U1.35@89.713,29.554
  Top Layer w0.2: v1(89.713,29.161) U1.35@89.713,29.554
  Signal Layer 3 w0.1: LCD1.9@54.4,23.8 54.467,23.733 54.467,19.304 v1(54.534,19.237)
  Signal Layer 4 w0.1: v1(54.534,19.237) 55.21,19.237 55.403,19.044 61.742,19.044 62.408,19.71 70.626,19.71 80.687,29.772 81.15,29.772 81.825,29.097 88.283,29.097 88.348,29.161 v1(89.713,29.161)
LCD_SEG9: LCD1.10 U1.40 | length 44.9
  Top Layer w0.1: U1.40@89.55,31.6 89.551,31.599 90.448,31.599 v1(90.449,31.598)
  Signal Layer 3 w0.1: LCD1.10@56.4,23.8 56.432,23.768 56.432,21.429 56.464,21.397 v1(56.464,19.437)
  Signal Layer 4 w0.1: v1(56.464,19.437) 61.728,19.437 62.281,19.99 70.622,19.99 80.604,29.972 81.306,29.972 81.395,29.882 89.547,29.882 90.449,30.785 v1(90.449,31.598)
LCD_SEG10: LCD1.11 U1.41 | length 47.3
  Top Layer w0.1: U1.41@89.55,32 90.8,32 90.898,31.902 v1(91.008,31.902)
  Signal Layer 3 w0.1: LCD1.11@58.4,23.8 58.4,18.647 58.519,18.528 58.519,18.155 v1(58.572,18.102)
  Signal Layer 4 w0.1: v1(58.572,18.102) 59.841,18.102 59.989,18.249 69.73,18.249 80.257,28.776 80.803,28.776 80.923,28.897 87.942,28.897 88.07,28.768 90.741,28.768 91.122,29.149 91.122,30.452 90.971,30.603 90.971,31.865 v1(91.008,31.902)
LCD_SEG11: LCD1.12 U1.43 | length 48.5
  Top Layer w0.1: U1.43@89.55,32.8 91.422,32.8 v1(91.424,32.798)
  Signal Layer 3 w0.1: LCD1.12@60.4,23.8 60.388,23.788 60.388,17.869 v1(60.401,17.856)
  Signal Layer 4 w0.1: v1(60.401,17.856) 60.464,17.794 61.177,17.794 61.37,17.986 69.75,17.986 80.34,28.576 80.886,28.576 81.006,28.697 87.86,28.697 87.988,28.568 91.556,28.568 92.364,29.376 92.364,30.829 92.364,31.03 92.368,31.034 92.368,31.322 91.424,32.266 v1(91.424,32.798)
LCD_SEG12: LCD1.13 U1.44 | length 47.9
  Top Layer w0.1: U1.44@89.55,33.2 92.042,33.2 v1(92.05,33.207)
  Signal Layer 3 w0.1: LCD1.13@62.4,23.8 62.4,20.162 62.611,19.951 v1(62.611,17.594)
  Signal Layer 4 w0.1: v1(62.611,17.594) 69.64,17.594 80.423,28.376 80.968,28.376 81.089,28.497 87.777,28.497 87.905,28.368 91.673,28.368 92.564,29.259 92.564,30.947 92.568,30.951 92.568,31.594 92.05,32.113 v1(92.05,33.207)
LCD_SEG13: LCD1.14 U1.28 | length 39.2
  Top Layer w0.1: U1.28@86.4,28.85 86.4,28.23 86.69,27.94 87.043,27.94 87.4,27.583 87.4,26.944 87.595,26.749 87.595,26.127 87.201,25.734 v1(87.201,25.68)
  Signal Layer 3 w0.1: LCD1.14@64.4,23.8 64.4,16.423 64.854,15.969 64.854,15.449 v1(64.922,15.381)
  Signal Layer 4 w0.1: v1(64.922,15.381) 69.679,15.381 78.781,24.482 86.004,24.482 v1(87.201,25.68)
LCD_SEG14: LCD1.15 U1.27 | length 49.1
  Top Layer w0.1: U1.27@86,28.85 86,28.249 86.714,27.535 86.892,27.535 v1(86.97,27.457)
  Signal Layer 3 w0.1: v1(86.97,27.457) 89.837,30.324 89.837,35.455 90.891,36.509 90.891,42.942 v1(89.713,44.12)
  Signal Layer 4 w0.1: LCD1.15@64.4,49.2 66.961,49.2 71.073,45.088 72.336,45.088 74.529,42.896 76.521,42.896 76.882,43.256 83.058,43.256 83.922,44.12 v1(89.713,44.12)
LCD_SEG15: LCD1.16 U1.15 | length 34.1
  Top Layer w0.1: v1(80.992,30.406) 80.996,30.403 81.647,30.403 U1.15@81.65,30.4
  Signal Layer 3 w0.1: v1(77.191,43.663) 77.978,42.875 77.978,31.96 78.755,31.183 78.882,31.183 79.659,30.406 v1(80.992,30.406)
  Signal Layer 4 w0.1: LCD1.16@62.4,49.2 62.56,49.2 63.41,50.05 66.394,50.05 71.156,45.288 74.066,45.288 75.413,43.942 76.899,43.942 77.178,43.663 v1(77.191,43.663)
LCD_SEG16: LCD1.17 U1.16 | length 35.2
  Top Layer w0.1: v1(79.33,30.17) 79.44,30.17 79.61,30 U1.16@81.65,30
  Signal Layer 3 w0.1: v1(77.107,42.565) 77.778,41.894 77.778,31.808 79.33,30.257 v1(79.33,30.17)
  Signal Layer 4 w0.1: LCD1.17@60.4,49.2 61.25,48.35 67.528,48.35 70.99,44.888 72.253,44.888 74.541,42.601 77.071,42.601 v1(77.107,42.565)
LCD_SEG17: LCD1.18 U1.45 | length 53.3
  Top Layer w0.1: U1.45@89.55,33.6 92.315,33.6 92.365,33.65 92.705,33.65 v1(92.769,33.714)
  Signal Layer 3 w0.1: v1(92.769,33.714) 93.25,34.195 93.25,39.094 93.726,39.57 93.726,41.885 v1(94.64,42.799)
  Signal Layer 4 w0.1: LCD1.18@58.4,49.2 59.515,48.085 67.51,48.085 70.907,44.688 72.17,44.688 74.687,42.172 78.743,42.172 79.418,42.846 79.422,42.846 79.429,42.853 82.985,42.853 83.81,43.678 91.577,43.678 92.456,42.799 v1(94.64,42.799)
LCD_SEG18: LCD1.19 U1.46 | length 56.1
  Top Layer w0.1: U1.46@89.55,34 91.834,34 91.972,34.138 v1(92.083,34.138)
  Signal Layer 3 w0.1: v1(91.796,46.914) 93.326,45.383 93.326,39.808 92.849,39.331 92.849,34.883 92.105,34.138 v1(92.083,34.138)
  Signal Layer 4 w0.1: LCD1.19@56.4,49.2 57.45,50.25 66.478,50.25 71.24,45.488 74.162,45.488 75.507,44.143 80.643,44.143 82.48,45.98 90.935,45.98 91.796,46.841 v1(91.796,46.914)
LCD_SEG19: LCD1.20 U1.47 | length 56.5
  Top Layer w0.1: U1.47@89.55,34.4 89.552,34.398 91.53,34.398 v1(91.532,34.396)
  Signal Layer 3 w0.1: v1(91.11,46.711) 91.11,46.076 91.948,45.237 91.948,36.551 92.571,35.928 92.571,34.888 92.341,34.658 91.842,34.658 91.58,34.396 v1(91.532,34.396)
  Signal Layer 4 w0.1: LCD1.20@54.4,49.2 54.4,49.247 54.447,49.247 55.65,50.45 66.561,50.45 71.323,45.688 74.298,45.688 75.643,44.343 80.487,44.343 82.324,46.18 90.681,46.18 91.11,46.609 v1(91.11,46.711)
LED_JLINK: LED901.2 TPJ912.1 U900.A7 | length 57
  Top Layer w0.1: U900.A7@48.5,38.5 48.5,38.139 48.543,38.096 48.543,37.741 48.604,37.68 48.604,37.395 v1(48.543,37.334)
  Top Layer w0.2: LED901.2@10.65,50.4 v1@11.25,50.4
  Signal Layer 4 w0.1: v1(11.45,50.4) 12.042,50.4 29.864,32.578 32.621,32.578 33.698,33.655 39.445,33.655 40.18,34.39 42.837,34.39 43.61,33.616 43.61,33.078 43.884,32.804 44.317,32.804 45.196,31.925 46.051,31.925 46.201,31.775 48.772,31.775 v1(49.461,32.464)
  Bottom Layer w0.1: v1(48.543,37.334) 48.543,35.48 49.798,34.225 TPJ912.1@50.751,34.225 50.751,33.48 50.747,33.475 50.747,33.147 50.446,32.846 49.742,32.846 49.461,32.564 v1(49.461,32.464)
LED_STATUS_G: LED904.3 U900.D13 | length 32.3
  Top Layer w0.1: v1(44.075,39.5) 44.075,39.582 44.777,40.284 45.216,40.284 U900.D13@45.5,40
  Top Layer w0.2: LED904.3@23.751,51.789 24.437,51.789 v1(24.46,51.765)
  Signal Layer 4 w0.1: v1(24.46,51.765) 24.003,51.765 22.708,50.47 22.708,48.514 30.061,41.161 43.043,41.161 44.075,40.129 v1(44.075,39.5)
LED_STATUS_R: LED904.4 U900.E13 | length 29.4
  Top Layer w0.1: v1(44.875,40.775) 45.225,40.775 U900.E13@45.5,40.5
  Top Layer w0.2: LED904.4@23.794,51.029 23.87,51.105 v1(24.486,51.105)
  Signal Layer 4 w0.1: v1(24.486,51.105) 23.292,49.911 23.292,48.433 30.125,41.6 30.272,41.453 43.217,41.453 43.894,40.775 v1(44.875,40.775)
LES_LC_SENSE: R126.1 R323.1 U1.23 | length 63.5
  Top Layer w0.1: R323.1@48.75,6.65 48.754,6.654 v1(48.754,7.947) ; v1(75.844,10.262) 78.338,10.262 R126.1@78.35,10.25 ; U1.23@84.4,28.85 84.4,28.525 84.731,28.194 84.88,28.194 85.779,27.295 85.779,26.797 85.662,26.68 85.662,26.679 85.444,26.461 85.444,26.02 86.434,25.031 v1(87.427,25.031)
  Signal Layer 4 w0.1: v1(48.754,7.947) 49.45,7.947 49.581,8.077 74.371,8.077 75.844,9.55 v1(75.844,10.262) 75.844,11.001 74.334,12.512 74.334,19.47 78.918,24.054 86.449,24.054 v1(87.427,25.031)
LFXTAL_I: U1.4 X2.2 | length 2
  Top Layer w0.1: X2.2@79.751,35.1 80.06,35.1 80.36,34.8 U1.4@81.65,34.8
LFXTAL_O: U1.5 X2.1 | length 2
  Top Layer w0.1: X2.1@79.751,34.1 80.071,34.1 80.321,34.35 80.324,34.35 80.374,34.4 U1.5@81.65,34.4
MCU_B6: R307.1 R317.1 U1.24 | length 53.7
  Top Layer w0.1: v1(50.521,7.671) 51.333,7.671 51.333,7.585 R307.1@51.3,7.552 ; R317.1@51.3,6.65 R307.1@51.3,7.552 ; R307.1@51.3,7.65 R307.1@51.3,7.552 ; U1.24@84.8,28.85 84.8,28.552 84.958,28.394 84.963,28.394 85.979,27.378 85.979,26.637 85.915,26.573 85.915,26.254 v1(85.841,26.179)
  Signal Layer 3 w0.1: v1(50.521,7.671) 50.521,15.939 v1(51.054,16.473)
  Signal Layer 4 w0.1: v1(51.054,16.473) 60.972,16.473 61.392,16.053 69.777,16.053 79.048,25.324 79.858,25.324 80.264,24.917 84.484,24.917 85.308,25.742 85.404,25.742 v1(85.841,26.179)
N16768220: R104.1 SW100.1 SW100.2 | length 5.2
  Top Layer w0.1: R104.1@49.35,14.05 50.4,14.05 SW100.1@50.425,14.075 SW100.2@54.575,14.075
N16768338: R105.1 SW101.1 SW101.2 | length 5.2
  Top Layer w0.1: R105.1@37.35,14.05 38.4,14.05 SW101.1@38.425,14.075 SW101.2@42.575,14.075
N16769621: LED101.1 R107.1 | length 0.9
  Top Layer w0.3: LED101.1@62.418,13.462 63.138,13.462 R107.1@63.3,13.3
N16769748: LED100.1 R106.1 | length 0.9
  Top Layer w0.3: R106.1@66.7,13.3 66.85,13.45 LED100.1@67.5,13.45
N16772319: C124.1 L125.1 R122.2 | length 6.9
  Top Layer w0.1: R122.2@79.25,11.15 80.05,11.15 C124.1@80.1,11.2 82.537,11.2 83.837,12.5 L125.1@85.6,12.5
N16772327: C124.2 L125.2 R126.2 | length 7.1
  Top Layer w0.1: R126.2@79.25,10.25 80.05,10.25 C124.2@80.1,10.2 80.15,10.15 82.178,10.15 82.803,9.525 83.828,8.5 L125.2@85.6,8.5
N16772335: C123.1 R121.2 R122.1 | length 1.7
  Top Layer w0.1: R121.2@76.65,11.15 C123.1@77.5,11.15 R122.1@78.35,11.15
N16780374: C115.1 D101.1 R114.1 R116.2 | length 3.3
  Top Layer w0.3: C115.1@95.9,31.975 95.9,31.2 R114.1@95.85,31.15 D101.1@95.85,30 97.15,30 R116.2@97.175,30.025
N16780620: R109.2 U102.6 U103.8 | length 6.6
  Top Layer w0.1: U103.8@105.188,51.136 105.188,51.376 105.272,51.46 106.68,51.46 106.85,51.29 R109.2@106.85,50.95 107.35,50.95 107.775,50.525 109.675,50.525 110.45,51.3 U102.6@110.45,51.5
N16780622: R108.2 U102.1 U103.11 | length 11.1
  Top Layer w0.1: v1(106.83,49.026) 106.84,49.036 106.84,49.49 R108.2@106.85,49.5 107.223,49.5 107.598,49.875 109.375,49.875 110.45,48.8 U102.1@110.45,48.6
  Top Layer w0.2: U103.11@103.988,51.136 103.988,51.968 v1(104.292,52.273)
  Signal Layer 3 w0.1: v1(104.292,52.273) 105.33,52.273 106.8,50.804 106.8,49.057 v1(106.83,49.026)
N16808623: C127.1 P100.1 R120.2 R128.1 | length 8.7
  Top Layer w0.1: C127.1@103.289,10.9 C127.1@103.302,10.9 ; R128.1@103.302,9.754 C127.1@103.302,10.9 ; P100.1@110.7,11 105.037,11 R120.2@104.845,10.807 104.752,10.9 C127.1@103.302,10.9
N16809528: D703.1 P700.1 Q703.3 ST701.2 | length 60.2
  Top Layer w0.5: ST701.2@2.875,4.62 3.82,4.62 v1@4.087,4.887 ; v1(4.087,4.981) v1@4.087,4.887 ; P700.1@7,6.078 5.278,6.078 v1@4.087,4.887 ; v1(10.046,4.981) 12.019,4.981 12.675,4.325 D703.1@13.2,4.325 14.525,4.325 14.8,4.6 Q703.3@14.8,5.325
  Top Layer w1: P700.1@5.947,5.025 P700.1@7,6.078
  Signal Layer 3 w0.6: v1(3.958,7.181) 3.958,4.988 3.962,4.984 3.962,4.981 v1(4.087,4.981) v1(10.046,4.981) v1(10.046,6.081) v1(10.046,7.181) 11.714,7.181 17.039,12.506 17.039,20.919 11.133,26.825 v1(10.046,26.825) v1(10.046,27.925) 10.046,29.025 v1(3.958,29.025) 3.958,29.023 3.962,29.019 v1(3.962,27.925) v1(3.962,26.825)
  other v1: 3.962,6.081
N16809565: Q703.2 SW704.6 TP156.1 | length 5.4
  Top Layer w0.5: Q703.2@15.3,3.65 Q703.2@15.325,3.625
  Top Layer w0.635: Q703.2@15.325,3.625 v1(15.8,3.625) 17.15,3.625 18.4,2.375 SW704.6@18.4,1.75
  Bottom Layer w0.3: TP156.1@15.3,4.6 15.8,4.1 v1(15.8,3.625)
N16809744: R793.1 SW704.1 | length 3.3
  Top Layer w0.25: SW704.1@23.4,7.25 23.4,7.538 23.862,8 R793.1@26.2,8
N16809746: R794.1 SW704.3 | length 3.1
  Top Layer w0.25: R794.1@15.7,7.95 17.938,7.95 18.4,7.488 SW704.3@18.4,7.25
N16811360: R7.2 SW1.3 SW1.4 | length 5.5
  Top Layer w0.1: R7.2@99.45,40.85 100.075,40.225 SW1.4@100.075,39.775 SW1.3@100.075,35.625
N16812963: Q703.1 R792.2 | length 0.8
  Top Layer w0.1: R792.2@14.275,2.9 R792.2@14.3,2.925
  Top Layer w0.25: R792.2@14.3,2.925 Q703.1@14.3,3.65
N16816128: L11.1 U1.52 | length 2.5
  Top Layer w0.2: U1.52@88.8,36.75 89.125,36.75 89.129,36.754
  Top Layer w0.8: 89.1,36.775 89.1,37.331 89.782,38.013 89.782,38.608 L11.1@89.847,38.673
N16831167: R700.1 U701.7 | length 1.2
  Top Layer w0.3: R700.1@29.459,25.222 29.469,25.222 29.589,25.342 U701.7@30.578,25.342
N16831188: C705.1 U701.6 | length 1.1
  Top Layer w0.25: C705.1@29.434,25.857 29.449,25.842 U701.6@30.578,25.842
N16831199: R702.1 R703.2 U701.5 | length 3.1
  Top Layer w0.25: U701.5@30.578,26.342 30.578,26.514
  Top Layer w0.35: U701.5@30.653,26.392 30.653,26.589 31.181,27.117 31.181,27.698 R703.2@31.406,27.924 R702.1@32.475,27.924
N16831281: R705.2 TP711.1 U702.11 | length 20.7
  Top Layer w0.1: v1(26.61,29.083) 27.006,29.083 27.041,29.118 27.041,29.403 27.473,29.403 27.789,29.719 U702.11@28.226,29.719
  Signal Layer 4 w0.1: v1(26.61,29.083) 26.111,29.582 26.111,31.394 27.095,32.378 32.704,32.378 33.727,33.401 39.362,33.401 39.822,32.941 v1(40.287,32.941)
  Bottom Layer w0.1: v1(40.287,32.941) 40.331,32.897 40.331,32.119 TP711.1@40.375,32.075
N16831285: R706.2 TP712.1 U702.8 | length 16.8
  Top Layer w0.1: v1(26.61,31.095) R706.2@27.31,31.095 ; R706.2@27.255,31.15 R706.2@27.31,31.095 ; U702.8@28.226,30.919 28.176,30.969 27.436,30.969 R706.2@27.31,31.095
  Signal Layer 4 w0.1: v1(26.61,31.095) 27.671,32.156 32.868,32.156 33.591,32.88 39.027,32.88 v1(39.05,32.857)
  Bottom Layer w0.1: v1(39.05,32.857) 39.05,32.88 39.7,33.53 TP712.1@39.7,34.4
N16831289: R707.2 TP713.1 U702.3 | length 17
  Top Layer w0.1: U702.3@29.996,30.119 30.021,30.144 30.786,30.144 30.817,30.175 v1(31.623,30.175)
  Signal Layer 4 w0.1: v1(31.623,30.175) 31.629,30.169 33.087,30.169 33.176,30.257 33.178,30.257 33.774,30.853 40.065,30.853 40.158,30.946 41.385,30.946 42.849,32.41 v1(44.155,32.41)
  Bottom Layer w0.1: v1(44.155,32.41) 44.155,32.412 44.526,32.783 44.526,33.516 44.255,33.788 TP713.1@44.255,34.025
N16831309: R708.2 TP714.1 U702.1 | length 16.8
  Top Layer w0.2: U702.1@29.996,29.319 30.236,29.319 30.399,29.156 30.407,29.156 v1(30.582,28.981)
  Top Layer w0.3: v1(30.582,28.981) R708.2@30.993,28.981
  Signal Layer 4 w0.1: v1(30.582,28.981) 30.582,29.489 30.81,29.718 32.919,29.718 33.258,30.057 33.261,30.057 33.857,30.653 40.148,30.653 40.241,30.746 41.49,30.746 42.504,31.76 v1(43.88,31.76)
  Bottom Layer w0.1: TP714.1@43.025,31.875 43.083,31.818 43.823,31.818 v1(43.88,31.76)
N16831821: C707.1 L702.2 U702.14 | length 3.2
  Top Layer w0.2: C707.1@29.083,28.19 29.134,28.24 29.134,28.702 29.311,28.879 U702.14@29.311,29.234
  Top Layer w0.3: L702.2@27.432,27.192 27.657,27.417 27.925,27.417 28.668,28.16 29.073,28.16 C707.1@29.073,28.22
N16839091: R709.1 U703.1 U703.2 | length 3.8
  Top Layer w0.1: U703.2@37.729,36.558 38.321,36.558 38.43,36.449 38.43,36.195 38.293,36.058 U703.1@37.729,36.058 37.772,36.058 37.846,35.984 37.846,34.822 38.343,34.325 R709.1@38.343,34.3
N16839103: C710.2 U703.6 | length 0.8
  Top Layer w0.25: C710.2@34.129,37.083 34.154,37.058 U703.6@34.929,37.058
N16839111: C729.1 R718.2 U703.4 U704.3 U704.5 | length 8.8
  Top Layer w0.1: U704.3@34.345,40.675 35.8,40.675 36.45,40.025 U704.5@38.556,40.025 38.556,38.682 R718.2@39.404,37.833
  Top Layer w0.25: U703.4@37.729,37.558 C729.1@38.504,37.558 38.504,37.578 38.539,37.613 39.184,37.613 R718.2@39.404,37.833
N16839131: R710.1 U703.8 | length 1.9
  Top Layer w0.1: R710.1@34.478,34.3 34.478,34.355 34.929,34.806 U703.8@34.929,36.058
N16839143: L700.2 R717.1 | length 1
  Top Layer w0.5: L700.2@30.808,35.195 R717.1@31.784,35.195
N16839420: C766.1 R765.1 R767.2 U704.2 | length 3.1
  Top Layer w0.1: R767.2@32.6,39.55 R765.1@32.6,40.6 33.025,41.025 C766.1@33.5,41.025 33.8,41.325 U704.2@34.345,41.325
N16839426: C766.2 R764.1 R765.2 U704.1 | length 3.6
  Top Layer w0.1: R764.1@32.525,43.275 32.525,42.075 R765.2@32.6,42 33.025,41.575 C766.2@33.5,41.575 33.5,41.9 33.575,41.975 U704.1@34.345,41.975
N16839472: C770.1 R769.1 R771.2 U704.6 | length 3.5
  Top Layer w0.1: U704.6@38.556,40.675 39.275,40.675 C770.1@39.4,40.8 39.7,40.5 39.9,40.5 R769.1@40.3,40.1 40,39.8 40,39.4 R771.2@39.6,39
N16839478: C770.2 R768.1 R769.2 U704.7 | length 3
  Top Layer w0.1: U704.7@38.556,41.325 38.581,41.35 C770.2@39.4,41.35 40.15,41.35 R769.2@40.3,41.5 R768.1@40.3,42.7
N16839586: C730.1 C731.1 R731.1 U704.8 | length 3.8
  Top Layer w0.5: R731.1@37.05,44.9 37.525,44.9 38.5,43.925 C731.1@38.5,43.8 38.555,43.745 U704.8@38.555,42.015
N16839602: L704.2 R731.2 | length 0.9
  Top Layer w0.5: L704.2@36.075,45.8 36.075,44.975 R731.2@36.15,44.9
N16846192: R808.2 U802.6 U802.12 U803.3 U806.5 U806.6 U806.12 U806.13 | length 42
  Top Layer w0.1: U803.3@57.521,34.599 58.212,34.599 58.601,34.211 59.036,34.211 v1(59.057,34.19) ; R808.2@67.876,31.506 67.893,31.488 67.893,31.244 68.09,31.047 68.353,31.047 68.7,30.7 U806.6@69.175,30.7 ; R808.2@67.886,31.496 69.029,31.496 69.181,31.344 70.053,31.344 71.36,32.65 U806.12@75.025,32.65 75.163,32.512 75.87,32.512 75.951,32.431 v1@76.23,32.431 ; U802.6@69.175,37.2 69.325,37.35 70.168,37.35 v1(70.207,37.389) ; v1@70.21,37.415 70.916,38.121 73.376,38.121 74.272,39.016 74.891,39.016 U802.12@75.025,39.15 75.072,39.103 v1(75.981,39.103) ; U806.13@75.025,33.3 75.153,33.172 75.784,33.172 76.214,32.743 76.214,32.447 v1(76.276,32.385)
  Signal Layer 3 w0.1: v1(75.981,39.103) 75.981,39.089 75.667,38.775 75.667,37.516 76.01,37.173 76.01,32.734 76.276,32.467 v1(76.276,32.385)
  Signal Layer 4 w0.1: v1(59.057,34.19) 59.946,34.19 60.604,34.849 60.604,35.387 61.983,36.766 62.729,36.766 62.905,36.59 69.001,36.59 69.799,37.389 v1(70.207,37.389)
N16846231: C804.1 C810.1 L801.2 U804.8 U809.8 | length 11.7
  Top Layer w0.2: C804.1@47.791,34.936 U804.8@48.686,34.936 ; v1(48.895,34.468) 48.895,34.929 48.888,34.936 U804.8@48.686,34.936 ; U804.8@48.953,34.954 48.703,34.954 U804.8@48.686,34.936 ; C810.1@53.225,36.055 53.245,36.055 53.305,36.115 53.305,36.467 53.398,36.56 U809.8@53.398,36.985 ; C810.1@53.244,36.036 53.247,36.033 53.247,35.546 54.016,34.777 v1@54.413,34.777
  Top Layer w0.3: v1@54.428,34.8 54.461,34.8 54.671,34.589 55.061,34.589 L801.2@55.15,34.5
  Signal Layer 4 w0.3: v1(48.895,34.468) 48.925,34.498 52.528,34.498 52.992,34.034 53.685,34.034 v1(54.428,34.777)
